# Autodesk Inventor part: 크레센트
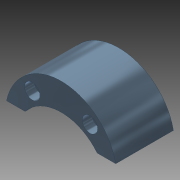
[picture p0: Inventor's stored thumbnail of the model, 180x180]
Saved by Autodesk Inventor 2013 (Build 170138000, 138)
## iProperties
Created: 2023-11
Part Number: 크레센트
Material: 강철, 합금
Document SubType Name: Modeling
Designer: mdu-01
Density: 1 g/cm^3
Author: mdu-01
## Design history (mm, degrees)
sketch "스케치1"
  geometry: L1 (-28.373, 15)-(-18.735, 15); L2 (18.735, 15)-(28.373, 15); A1 r 24 centre (0, 0) between (-18.735, 15) and (18.735, 15); A2 r 29 centre (0, 9) between (-28.373, 15) and (28.373, 15); 1 further point
  constraints: 4 end point, 4 point on circle, 2 centre point, 2 horizontal, 1 coincident, 1 collinear, 1 vertical alignment
  dimensions: "d0" = 9 distance of A2.centre A1.centre; "d2" = 48 diameter of A1; "d3" = 58 diameter of A2; "d5" = 6 distance from line of L2 A2.centre
extrude "돌출1" new body sketch "스케치1" distance "d6" = 30; taper "d7" = 0 deg
sketch "스케치2"
  geometry: L1 (-15, 26)-(15, 26); L2 (18.735, 15)-(28.373, 15) reference; 2 further points
  constraints: 2 end point, 1 horizontal, 1 midpoint, 1 vertical alignment
  dimensions: "d8" = 11 distance between parallel lines of L1 L2; "d9" = 30 distance of L1.start L1.end
hole "구멍1" sketch "스케치2" at (15, 26), (-15, 26) diameter "d10" = 4.5; stored, may be unused: countersink angle "d14" = 90 deg, drill point angle "d16" = 118 deg; dims "d11" = 6, "d12" = 8, "d13" = 5, "d15" = 8
node "솔리드1"
other parameters: "d4" = 6
